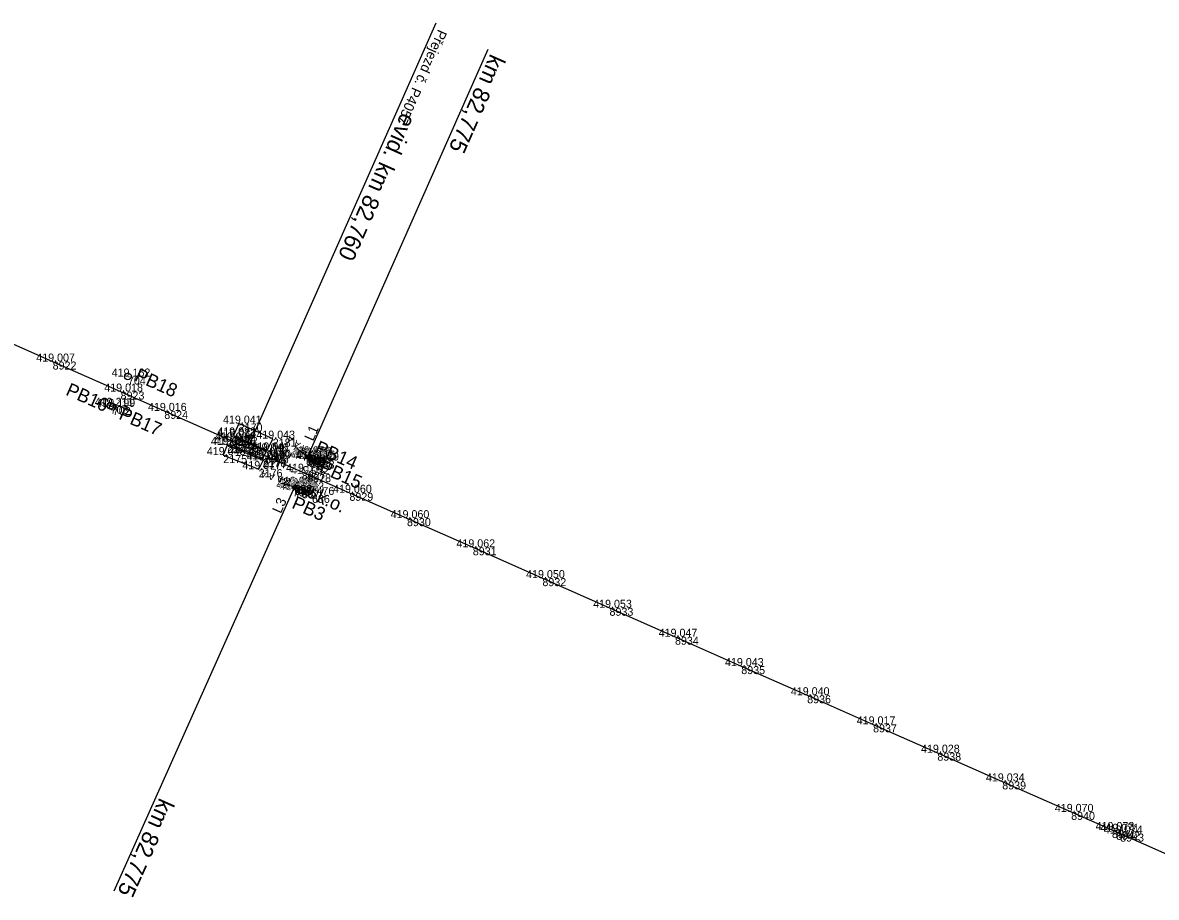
# Model space of a CAD drawing. Extents: x -599511 to -595511, y -1067427 to -1062061.
# Drawn here: x -599166.7 to -598996.7, y -1062335.4 to -1062204.3 of the extents above; entities that cross this region are included whole.
import ezdxf

# ---------------------------------------------------------------- set-up
doc = ezdxf.new("R2010")
doc.units = 0
for name, color, linetype in [('Vrstva 1', 7, 'Continuous'), ('Vrstva 12', 7, 'Continuous'), ('Vrstva 27', 7, 'Continuous'), ('Vrstva 4', 7, 'Continuous'), ('Vrstva 49', 7, 'Continuous'), ('Vrstva 6', 7, 'Continuous'), ('Vrstva 60', 7, 'Continuous'), ('Vrstva 61', 7, 'Continuous')]:
    doc.layers.add(name, color=color, linetype=linetype)

msp = doc.modelspace()

# ---------------------------------------------------------------- linework, layer by layer
at = {"layer": 'Vrstva 1'}
msp.add_lwpolyline([(-599172.3, -1062250.62), (-599162.24, -1062255.06), (-599152.05, -1062259.56), (-599145.5, -1062262.46), (-599135.46, -1062266.89), (-599130.42, -1062269.12), (-599124.88, -1062271.57), (-599124.07, -1062271.93), (-599117.74, -1062274.73), (-599109.11, -1062278.53), (-599099.24, -1062282.9), (-599088.8, -1062287.52), (-599078.74, -1062291.96), (-599068.92, -1062296.3), (-599058.98, -1062300.7), (-599049.1, -1062305.07), (-599039.22, -1062309.43), (-599029.58, -1062313.68), (-599019.85, -1062317.98), (-599009.52, -1062322.55), (-599003.4, -1062325.26), (-599002.78, -1062325.53), (-599002.16, -1062325.8), (-598991.2, -1062330.65)], dxfattribs=at)
at = {"layer": 'Vrstva 12'}
for points in [[(-599124, -1062268.97), (-599123.64, -1062269.13), (-599123.88, -1062269.68), (-599124.24, -1062269.52)], [(-599125.88, -1062274.25), (-599126.24, -1062274.08), (-599126, -1062273.53), (-599125.64, -1062273.7)]]:
    msp.add_lwpolyline(points, close=True, dxfattribs=at)
at = {"layer": 'Vrstva 27'}
for p, q in [((-599150.99, -1062257.29), (-599150.9, -1062257.33)), ((-599153.6, -1062261.67), (-599153.51, -1062261.71)), ((-599153.27, -1062261.84), (-599153.18, -1062261.88)), ((-599123.26, -1062269.6), (-599123.17, -1062269.65)), ((-599122.7, -1062269.88), (-599122.61, -1062269.92)), ((-599124.92, -1062274.35), (-599124.83, -1062274.39)), ((-599123.41, -1062275.03), (-599123.32, -1062275.08))]:
    msp.add_line(p, q, dxfattribs=at)
for centre in [(-599150.95, -1062257.31), (-599153.56, -1062261.69), (-599153.22, -1062261.86), (-599123.22, -1062269.62), (-599122.65, -1062269.9), (-599124.88, -1062274.37), (-599123.36, -1062275.05)]:
    msp.add_circle(centre, 0.5, dxfattribs=at)
at = {"layer": 'Vrstva 4'}
msp.add_line((-599132.97, -1062267.99), (-599104.71, -1062204.28), dxfattribs=at)
for points in [[(-599130.07, -1062268.38), (-599129.24, -1062266.62), (-599134.34, -1062264.36), (-599135.1, -1062266.13)], [(-599130.77, -1062269.64), (-599135.62, -1062267.51), (-599135.08, -1062266.37), (-599130.24, -1062268.51)], [(-599131.34, -1062271.19), (-599130.69, -1062269.88), (-599136.06, -1062267.57), (-599136.66, -1062269.08)]]:
    msp.add_lwpolyline(points, close=True, dxfattribs=at)
at = {"layer": 'Vrstva 49'}
for p, q in [((-599124.23, -1062269.45), (-599123.76, -1062269.27)), ((-599124.09, -1062269.13), (-599123.91, -1062269.6)), ((-599126.17, -1062273.89), (-599125.7, -1062273.71)), ((-599126.03, -1062273.57), (-599125.85, -1062274.04))]:
    msp.add_line(p, q, dxfattribs=at)
at = {"layer": 'Vrstva 6'}
for p, q in [((-599123.96, -1062269.31), (-599096.93, -1062208.26)), ((-599125.54, -1062268.12), (-599123.96, -1062269.31)), ((-599124.26, -1062269.71), (-599123.66, -1062268.91)), ((-599127.88, -1062273.3), (-599125.98, -1062273.86)), ((-599126.12, -1062274.33), (-599125.84, -1062273.38)), ((-599125.98, -1062273.86), (-599153.08, -1062334.45))]:
    msp.add_line(p, q, dxfattribs=at)
at = {"layer": 'Vrstva 60'}
for p, q in [((-599162.24, -1062255.06), (-599162.24, -1062255.06)), ((-599150.95, -1062257.31), (-599150.95, -1062257.31)), ((-599152.05, -1062259.56), (-599152.05, -1062259.56)), ((-599153.56, -1062261.69), (-599153.56, -1062261.69)), ((-599153.22, -1062261.86), (-599153.22, -1062261.86)), ((-599145.5, -1062262.46), (-599145.5, -1062262.46)), ((-599134.34, -1062264.36), (-599134.34, -1062264.36)), ((-599135.46, -1062266.89), (-599135.46, -1062266.89)), ((-599135.1, -1062266.13), (-599135.1, -1062266.13)), ((-599135.08, -1062266.37), (-599135.08, -1062266.37)), ((-599129.24, -1062266.62), (-599129.24, -1062266.62)), ((-599136.06, -1062267.57), (-599136.06, -1062267.57)), ((-599135.62, -1062267.51), (-599135.62, -1062267.51)), ((-599130.24, -1062268.51), (-599130.24, -1062268.51)), ((-599130.07, -1062268.38), (-599130.07, -1062268.38)), ((-599136.66, -1062269.08), (-599136.66, -1062269.08)), ((-599130.77, -1062269.64), (-599130.77, -1062269.64)), ((-599130.69, -1062269.88), (-599130.69, -1062269.88)), ((-599130.42, -1062269.12), (-599130.42, -1062269.12)), ((-599124.24, -1062269.52), (-599124.24, -1062269.52)), ((-599124, -1062268.97), (-599124, -1062268.97)), ((-599124, -1062269.36), (-599124, -1062269.36)), ((-599123.96, -1062269.31), (-599123.96, -1062269.31)), ((-599123.88, -1062269.68), (-599123.88, -1062269.68)), ((-599123.64, -1062269.13), (-599123.64, -1062269.13)), ((-599123.22, -1062269.62), (-599123.22, -1062269.62)), ((-599122.65, -1062269.9), (-599122.65, -1062269.9)), ((-599131.34, -1062271.19), (-599131.34, -1062271.19)), ((-599124.88, -1062271.57), (-599124.88, -1062271.57)), ((-599124.07, -1062271.93), (-599124.07, -1062271.93)), ((-599126, -1062273.53), (-599126, -1062273.53)), ((-599125.94, -1062273.8), (-599125.94, -1062273.8)), ((-599125.64, -1062273.7), (-599125.64, -1062273.7)), ((-599126.24, -1062274.08), (-599126.24, -1062274.08)), ((-599125.98, -1062273.86), (-599125.98, -1062273.86)), ((-599125.88, -1062274.25), (-599125.88, -1062274.25)), ((-599124.88, -1062274.37), (-599124.88, -1062274.37)), ((-599123.36, -1062275.05), (-599123.36, -1062275.05)), ((-599117.74, -1062274.73), (-599117.74, -1062274.73)), ((-599109.11, -1062278.53), (-599109.11, -1062278.53)), ((-599099.24, -1062282.9), (-599099.24, -1062282.9)), ((-599088.8, -1062287.52), (-599088.8, -1062287.52)), ((-599078.74, -1062291.96), (-599078.74, -1062291.96)), ((-599068.92, -1062296.3), (-599068.92, -1062296.3)), ((-599058.98, -1062300.7), (-599058.98, -1062300.7)), ((-599049.1, -1062305.07), (-599049.1, -1062305.07)), ((-599039.22, -1062309.43), (-599039.22, -1062309.43)), ((-599029.58, -1062313.68), (-599029.58, -1062313.68)), ((-599019.85, -1062317.98), (-599019.85, -1062317.98)), ((-599009.52, -1062322.55), (-599009.52, -1062322.55)), ((-599003.4, -1062325.26), (-599003.4, -1062325.26)), ((-599002.78, -1062325.53), (-599002.78, -1062325.53)), ((-599002.16, -1062325.8), (-599002.16, -1062325.8))]:
    msp.add_line(p, q, dxfattribs=at)

# ---------------------------------------------------------------- texts
at = {"layer": 'Vrstva 27'}
for s, rotation, p in [('PB18', 336.1277, (-599150.09, -1062257.82)), ('PB16', 336.1602, (-599160.41, -1062260.01)), ('PB17', 336.1602, (-599152.45, -1062263.62)), ('PB14', 336.116, (-599123.08, -1062268.66)), ('PB15', 336.1384, (-599122.39, -1062271.57)), ('PB3', 336.1384, (-599126.53, -1062276.97)), ('k.o.', 336.1384, (-599122.8, -1062276.04))]:
    msp.add_text(s, height=2, rotation=rotation, dxfattribs=at).set_placement(p)
at = {"layer": 'Vrstva 4'}
for s, height, p in [('Přejezd č. P4057', 1.5, (-599104.43, -1062205.18)), ('evid. km 82,760', 2.5, (-599109.94, -1062217.64))]:
    msp.add_text(s, height=height, rotation=246.081, dxfattribs=at).set_placement(p)
at = {"layer": 'Vrstva 6'}
for s, height, rotation, p in [('km 82,775', 2.5, 246.1185, (-599096.58, -1062208.83)), ('L1', 1.5, 66.1185, (-599123.19, -1062267.08)), ('  A A A ', 1, 143.0955, (-599123.36, -1062268.51)), ('  A A A A ', 1, 163.7193, (-599125.7, -1062272.9)), ('L3', 1.5, 65.9067, (-599128.02, -1062277.93)), ('km 82,775', 2.5, 245.9067, (-599146.21, -1062320.33))]:
    msp.add_text(s, height=height, rotation=rotation, dxfattribs=at).set_placement(p)
at = {"layer": 'Vrstva 60'}
for s, p in [('8922', (-599162.24, -1062256.26)), ('704', (-599150.95, -1062258.51)), ('8923', (-599152.05, -1062260.76)), ('703', (-599153.56, -1062262.89)), ('702', (-599153.22, -1062263.06)), ('8924', (-599145.5, -1062263.66)), ('2170', (-599134.34, -1062265.56)), ('8925', (-599135.46, -1062268.09)), ('2171', (-599135.1, -1062267.33)), ('2172', (-599135.08, -1062267.57)), ('2181', (-599129.24, -1062267.82)), ('2174', (-599136.06, -1062268.77)), ('2173', (-599135.62, -1062268.71)), ('2179', (-599130.24, -1062269.71)), ('2180', (-599130.07, -1062269.57)), ('2175', (-599136.66, -1062270.28)), ('2178', (-599130.77, -1062270.84)), ('2177', (-599130.69, -1062271.08)), ('8926', (-599130.42, -1062270.32)), ('693', (-599124.24, -1062270.72)), ('690', (-599124, -1062270.17)), ('695', (-599124, -1062270.56)), ('694', (-599123.96, -1062270.51)), ('692', (-599123.88, -1062270.88)), ('691', (-599123.64, -1062270.33)), ('689', (-599123.22, -1062270.82)), ('688', (-599122.65, -1062271.1)), ('2176', (-599131.34, -1062272.39)), ('8927', (-599124.88, -1062272.77)), ('8928', (-599124.07, -1062273.13)), ('698', (-599126, -1062274.73)), ('697', (-599125.98, -1062275.05)), ('696', (-599125.94, -1062275)), ('699', (-599125.64, -1062274.9)), ('701', (-599126.24, -1062275.28)), ('700', (-599125.88, -1062275.45)), ('687', (-599124.88, -1062275.57)), ('686', (-599123.36, -1062276.25)), ('8929', (-599117.74, -1062275.93)), ('8930', (-599109.11, -1062279.73)), ('8931', (-599099.24, -1062284.1)), ('8932', (-599088.8, -1062288.72)), ('8933', (-599078.74, -1062293.16)), ('8934', (-599068.92, -1062297.5)), ('8935', (-599058.98, -1062301.9)), ('8936', (-599049.1, -1062306.27)), ('8937', (-599039.22, -1062310.63)), ('8938', (-599029.58, -1062314.88)), ('8939', (-599019.85, -1062319.18)), ('8940', (-599009.52, -1062323.75)), ('8941', (-599003.4, -1062326.46)), ('8942', (-599002.78, -1062326.73)), ('8943', (-599002.16, -1062327))]:
    msp.add_text(s, height=1.2, dxfattribs=at).set_placement(p)
at = {"layer": 'Vrstva 61'}
for s, p in [('419.007', (-599164.7, -1062255.06)), ('419.162', (-599153.39, -1062257.31)), ('419.018', (-599154.5, -1062259.56)), ('419.211', (-599155.92, -1062261.69)), ('419.199', (-599155.67, -1062261.86)), ('419.016', (-599147.95, -1062262.46)), ('419.041', (-599136.7, -1062264.36)), ('419.022', (-599137.55, -1062266.13)), ('419.033', (-599137.53, -1062266.37)), ('419.022', (-599138.51, -1062267.57)), ('419.035', (-599138.07, -1062267.51)), ('419.034', (-599137.91, -1062266.89)), ('419.043', (-599131.7, -1062266.62)), ('419.048', (-599139.12, -1062269.08)), ('419.049', (-599133.23, -1062269.64)), ('419.037', (-599133.14, -1062269.88)), ('419.050', (-599132.87, -1062269.12)), ('419.046', (-599132.7, -1062268.51)), ('419.041', (-599132.43, -1062268.38)), ('419.050', (-599126.69, -1062269.52)), ('419.050', (-599126.45, -1062269.36)), ('419.050', (-599126.41, -1062269.31)), ('419.051', (-599126.36, -1062268.97)), ('419.049', (-599126.33, -1062269.68)), ('419.052', (-599126.09, -1062269.13)), ('419.115', (-599125.68, -1062269.62)), ('419.129', (-599125.1, -1062269.9)), ('419.077', (-599133.79, -1062271.19)), ('419.051', (-599127.24, -1062271.57)), ('419.052', (-599126.52, -1062271.93)), ('419.055', (-599128.7, -1062274.08)), ('419.054', (-599128.45, -1062273.53)), ('419.052', (-599128.43, -1062273.86)), ('419.052', (-599128.39, -1062273.8)), ('419.051', (-599128.24, -1062274.25)), ('419.052', (-599128.09, -1062273.7)), ('419.093', (-599127.33, -1062274.37)), ('419.476', (-599125.81, -1062275.05)), ('419.060', (-599120.19, -1062274.73)), ('419.060', (-599111.56, -1062278.53)), ('419.062', (-599101.69, -1062282.9)), ('419.050', (-599091.25, -1062287.52)), ('419.053', (-599081.19, -1062291.96)), ('419.047', (-599071.37, -1062296.3)), ('419.043', (-599061.43, -1062300.7)), ('419.040', (-599051.55, -1062305.07)), ('419.017', (-599041.67, -1062309.43)), ('419.028', (-599032.03, -1062313.68)), ('419.034', (-599022.3, -1062317.98)), ('419.070', (-599011.97, -1062322.55)), ('419.073', (-599005.85, -1062325.26)), ('419.071', (-599005.13, -1062325.53)), ('419.074', (-599004.61, -1062325.8))]:
    msp.add_text(s, height=1.2, dxfattribs=at).set_placement(p)

doc.saveas('drawing.dxf')
